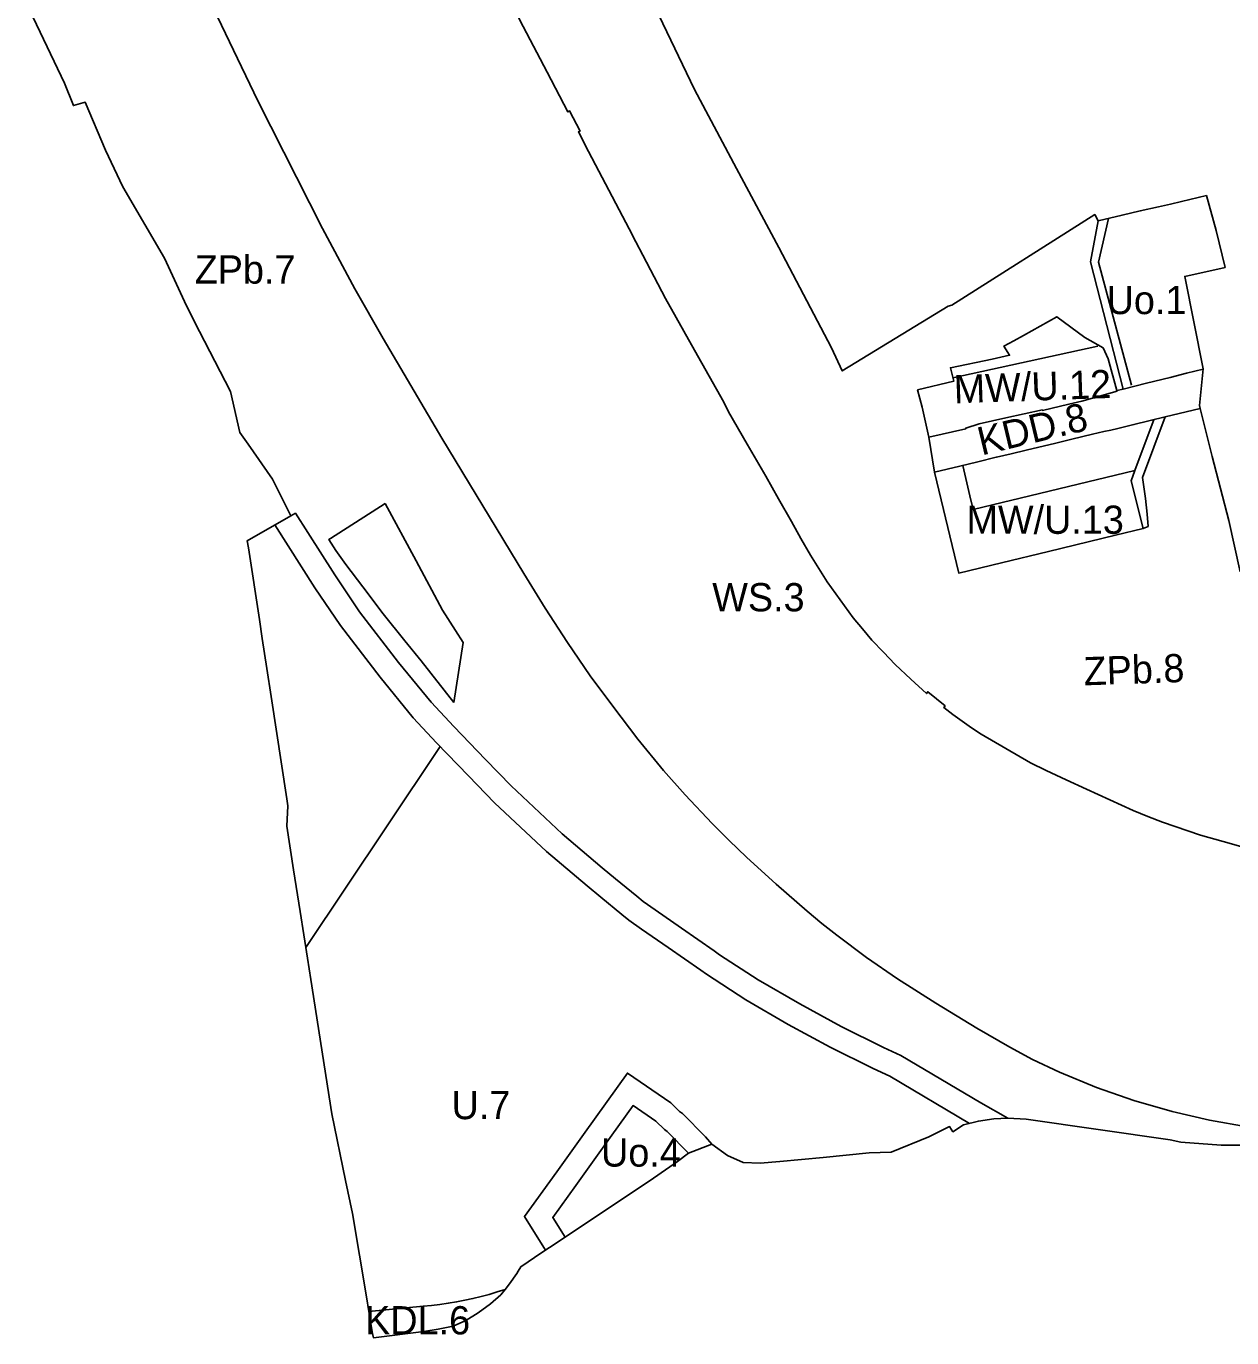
# Model space of a CAD drawing. Extents: x 7421697 to 7426767, y 5545731 to 5547485.
# Drawn here: x 7423591 to 7424103, y 5545804 to 5546361 of the extents above; entities that cross this region are included whole.
import ezdxf

# ---------------------------------------------------------------- set-up
doc = ezdxf.new("R2010")
doc.units = 0
for name, color, linetype in [('LIN_linia regulacyjna', 7, 'Continuous'), ('LIN_Linia Zabudowy Nieprzekraczalna', 7, 'Continuous'), ('LIN_linie_rozgraniczajace', 7, 'Continuous'), ('TXT_oznaczenia_przeznaczen', 7, 'Continuous')]:
    doc.layers.add(name, color=color, linetype=linetype)

msp = doc.modelspace()

# ---------------------------------------------------------------- linework, layer by layer
at = {"layer": 'LIN_linia regulacyjna'}
for p, q in [((7423766.42, 5546054.68), (7423743.61, 5546020.65)), ((7423743.61, 5546020.65), (7423709.27, 5545969.41))]:
    msp.add_line(p, q, dxfattribs=at)
for points in [[(7424063.77, 5546178.03), (7424069.56, 5546193.49)], [(7423991.42, 5546161.09), (7423992.75, 5546155.38), (7424061.5, 5546171.94), (7424063.77, 5546178.03)], [(7423988.4, 5546173.98), (7423991.42, 5546161.09)]]:
    msp.add_lwpolyline(points, dxfattribs=at)
at = {"layer": 'LIN_Linia Zabudowy Nieprzekraczalna'}
for p, q in [((7424045.78, 5546224.78), (7423984.11, 5546211.26)), ((7423743.06, 5546157.87), (7423719.82, 5546143.08)), ((7423772.2, 5546073.46), (7423776.13, 5546098.81))]:
    msp.add_line(p, q, dxfattribs=at)
for points in [[(7424050.23, 5546278.96), (7424045.99, 5546260.44), (7424060.07, 5546208.09)], [(7424064.95, 5546147.23), (7424059.83, 5546167.51), (7424061.49, 5546171.94)], [(7423776.13, 5546098.81), (7423772.84, 5546104.02), (7423767.4, 5546112.65), (7423756.15, 5546133.55), (7423743.06, 5546157.87)], [(7423991.24, 5545894.67), (7423957.33, 5545914.69), (7423950.32, 5545917.94), (7423932.02, 5545926.98), (7423914.18, 5545936.67), (7423896.14, 5545947.17), (7423879.49, 5545958.01), (7423877.03, 5545959.71), (7423863.17, 5545969.37), (7423851.94, 5545977.19), (7423846.5, 5545980.98), (7423843.54, 5545983.41), (7423834.56, 5545990.77), (7423828.77, 5545995.52), (7423811.54, 5546010.19), (7423789.48, 5546030.86), (7423778.4, 5546042.2), (7423764.84, 5546056.32), (7423754.96, 5546066.95), (7423740.85, 5546084.21), (7423724, 5546106.07), (7423713.19, 5546122.15), (7423696.2, 5546148.8)], [(7423719.82, 5546143.08), (7423719.07, 5546142.6), (7423722.11, 5546137.99), (7423726.32, 5546132), (7423733.5, 5546122.46), (7423742.18, 5546111.01), (7423751.29, 5546099.62), (7423758.29, 5546091.03), (7423772.2, 5546073.46)], [(7423811.08, 5545840.81), (7423802.15, 5545855.11), (7423815.91, 5545874.15), (7423827.93, 5545890.97), (7423845.89, 5545916), (7423864.38, 5545903.38), (7423868.08, 5545899.74), (7423869.35, 5545898.83), (7423879, 5545889), (7423881.73, 5545885.8)]]:
    msp.add_lwpolyline(points, dxfattribs=at)
at = {"layer": 'LIN_linie_rozgraniczajace'}
for points in [[(7423888.81, 5546196.87), (7423886.82, 5546200.98), (7423874.46, 5546223), (7423862.11, 5546245.01), (7423857.28, 5546254.19), (7423852.44, 5546263.37), (7423849.52, 5546268.96), (7423846.59, 5546274.55), (7423833.79, 5546299.08), (7423829.43, 5546307.39), (7423825.08, 5546315.69), (7423825.83, 5546316.03), (7423821.34, 5546324.6), (7423820.65, 5546324.21), (7423811.84, 5546341.04), (7423801.68, 5546360.42), (7423786.55, 5546389.63), (7423777.35, 5546407.77), (7423769.51, 5546423.7), (7423758.58, 5546446.87), (7423754.31, 5546456.24), (7423750.05, 5546465.61), (7423742.71, 5546481.91), (7423737.86, 5546492.89)], [(7424109.13, 5545893.25), (7424093.15, 5545896.05), (7424077.31, 5545899.76), (7424060.98, 5545904.43), (7424045.1, 5545909.88), (7424029.43, 5545916.36), (7424017.92, 5545921.85), (7424008.3, 5545926.98), (7423994.31, 5545935.05), (7423976.97, 5545945.7), (7423960.67, 5545956.05), (7423947.41, 5545965.11), (7423934.81, 5545974.58), (7423928.42, 5545979.6), (7423922.22, 5545984.79), (7423909.02, 5545996.25), (7423896.5, 5546007.68), (7423889.11, 5546014.73), (7423881.96, 5546022.03), (7423870.41, 5546034.24), (7423861.28, 5546044.45), (7423850.39, 5546057.76), (7423839.7, 5546071.82), (7423830.1, 5546084.79), (7423820.41, 5546098.84), (7423811, 5546113.42), (7423801.97, 5546128.12), (7423767.08, 5546185.68), (7423742.08, 5546228.03), (7423730.07, 5546249.1), (7423716.41, 5546274.66), (7423688.92, 5546328.84), (7423666.53, 5546375.63)], [(7424108.1, 5545885.42), (7424098.05, 5545885.35), (7424080.98, 5545886.74), (7424076.38, 5545887.66), (7424015.23, 5545896.5), (7424007.5, 5545896.87), (7424001.61, 5545896.53), (7423995.01, 5545895.67), (7423988.73, 5545894.01), (7423984.17, 5545891.11), (7423982.72, 5545893.33), (7423973.98, 5545888.99), (7423957.92, 5545882.39), (7423948.55, 5545882.22), (7423929.11, 5545880.16), (7423910.67, 5545878.55), (7423902.26, 5545877.74), (7423895.01, 5545878.1), (7423888.46, 5545881.02), (7423881.73, 5545885.8), (7423871.86, 5545881.99), (7423867.24, 5545878.49), (7423856.95, 5545871.34), (7423819.39, 5545846.37), (7423812.79, 5545841.95), (7423809.6, 5545839.82), (7423800.58, 5545833.77), (7423799.56, 5545831.85), (7423798.87, 5545830.86), (7423795.85, 5545826.51), (7423793.98, 5545824.18), (7423792.09, 5545821.84), (7423787.71, 5545818.07), (7423782.57, 5545814.23), (7423777.24, 5545810.97), (7423771.92, 5545808.58), (7423765.48, 5545807.26), (7423759.46, 5545806.26), (7423738, 5545803.63), (7423737.68, 5545805.5), (7423736.55, 5545812.22), (7423736.12, 5545814.75), (7423735.06, 5545821.05), (7423729.09, 5545856.42), (7423726.17, 5545870.48), (7423720.3, 5545898.69), (7423711.38, 5545955.82), (7423709.99, 5545964.79), (7423706.88, 5545984.7), (7423704.12, 5546002.34), (7423701.22, 5546020.93), (7423701.72, 5546029.57), (7423701.27, 5546032.53), (7423694.61, 5546075.92), (7423692.77, 5546087.84), (7423690.8, 5546100.64), (7423689.58, 5546108.6), (7423684.89, 5546139.1), (7423684.44, 5546142.05), (7423702.94, 5546152.67), (7423695.13, 5546168.29), (7423684.79, 5546183.08), (7423681.23, 5546188.06), (7423677.33, 5546205.48), (7423661.9, 5546235.37), (7423659.84, 5546239.38), (7423658.61, 5546241.81), (7423649.28, 5546262.07), (7423631.62, 5546292.35), (7423624.14, 5546307.98), (7423615.52, 5546328.33), (7423610.61, 5546326.9), (7423606.78, 5546336.34), (7423590.53, 5546370.45)], [(7423859.24, 5546365.27), (7423874.37, 5546333.67), (7423892.28, 5546300.17), (7423910.19, 5546266.66), (7423932.61, 5546223.95), (7423937.14, 5546214.2), (7423982.18, 5546241.75), (7423983.72, 5546242.11), (7424044.41, 5546280.59), (7424045.88, 5546277.87), (7424056.01, 5546280.41), (7424063.77, 5546282.17), (7424071.54, 5546283.94), (7424076.53, 5546285.07), (7424081.26, 5546286.15), (7424091.83, 5546288.66), (7424096, 5546273.89), (7424099.79, 5546258.14), (7424082.61, 5546254.35), (7424090.45, 5546215.13), (7424088.86, 5546199.57), (7424089.18, 5546198.28), (7424094.35, 5546177.91), (7424101.33, 5546150.7), (7424106.15, 5546128.94)], [(7424045.88, 5546277.87), (7424042.64, 5546260.52), (7424056.47, 5546206.44)], [(7423973.87, 5546186.1), (7423971.04, 5546198.75), (7423969.16, 5546206.19), (7423984.62, 5546209.86), (7423983.11, 5546215.52), (7424000.85, 5546219.26), (7424008.21, 5546220.87), (7424005.86, 5546224.76), (7424010, 5546227.03), (7424014.13, 5546229.29), (7424028.27, 5546237.18), (7424040.17, 5546228.42), (7424047.92, 5546224.03), (7424050.06, 5546219.38), (7424053.81, 5546205.84)], [(7424090.42, 5546214.9), (7424083.43, 5546213.19), (7424076.43, 5546211.47), (7424066.45, 5546208.96), (7424056.47, 5546206.44), (7424053.81, 5546205.84), (7424053.88, 5546205.61), (7424038.95, 5546201.4), (7424033.47, 5546200.06), (7424022.19, 5546197.45), (7424022.15, 5546197.62), (7424006.61, 5546194.24), (7423995.25, 5546191.78), (7423989.61, 5546189.93), (7423989.68, 5546189.64), (7423973.87, 5546186.1), (7423976.31, 5546171.16), (7423981.7, 5546172.44), (7423987.09, 5546173.71), (7423994.79, 5546175.61), (7424002.49, 5546177.51), (7424002.72, 5546177.57), (7424008.97, 5546179.03), (7424015.22, 5546180.49), (7424027.9, 5546183.56), (7424034.66, 5546185.15), (7424043.43, 5546187.32), (7424045.86, 5546187.87), (7424048.28, 5546188.42), (7424051.24, 5546189.09), (7424054.2, 5546189.77), (7424061.04, 5546191.41), (7424074.27, 5546194.64), (7424089.18, 5546198.28)], [(7424108.51, 5546011.67), (7424098.91, 5546014.37), (7424089.3, 5546017.07), (7424073.25, 5546022.52), (7424066.97, 5546025.02), (7424060.69, 5546027.52), (7424040.84, 5546036.57), (7424032.33, 5546040.52), (7424023.81, 5546044.48), (7424017.08, 5546047.82), (7424006.61, 5546053.87), (7423996.15, 5546059.92), (7423992.11, 5546062.68), (7423988.07, 5546065.44), (7423984.19, 5546068.34), (7423980.31, 5546071.25), (7423980.81, 5546071.92), (7423973.47, 5546077.95), (7423972.94, 5546077.21), (7423966.26, 5546083.37), (7423959.57, 5546089.52), (7423954.65, 5546094.71), (7423949.72, 5546099.9), (7423945.73, 5546104.66), (7423941.74, 5546109.41), (7423936.25, 5546117), (7423930.77, 5546124.59), (7423927.21, 5546130.24), (7423923.64, 5546135.9), (7423919.61, 5546143.05), (7423915.57, 5546150.2), (7423910.12, 5546159.82), (7423904.67, 5546169.44), (7423896.74, 5546183.15), (7423888.81, 5546196.87)], [(7423976.31, 5546171.16), (7423986.64, 5546128.34), (7424004.81, 5546132.72), (7424024.72, 5546137.52), (7424053.19, 5546144.39), (7424064.95, 5546147.23), (7424067.1, 5546148.16), (7424066.74, 5546153.35), (7424065.98, 5546160.09), (7424064.66, 5546169), (7424074.27, 5546194.64)], [(7423702.94, 5546152.67), (7423704.89, 5546153.79), (7423710.13, 5546145.56), (7423721.55, 5546127.63), (7423732.12, 5546111.91), (7423748.68, 5546090.43), (7423762.5, 5546073.53), (7423772.11, 5546063.19), (7423785.59, 5546049.15), (7423796.48, 5546038.01), (7423818.21, 5546017.65), (7423835.19, 5546003.19), (7423840.9, 5545998.5), (7423849.88, 5545991.15), (7423852.54, 5545988.96), (7423857.66, 5545985.4), (7423868.88, 5545977.58), (7423882.74, 5545967.92), (7423885.07, 5545966.3), (7423901.38, 5545955.69), (7423919.09, 5545945.39), (7423936.63, 5545935.86), (7423954.64, 5545926.96), (7423961.98, 5545923.55), (7423996.07, 5545903.43), (7424007.5, 5545896.87)], [(7423819.39, 5545846.37), (7423814.19, 5545854.7), (7423824.03, 5545868.31), (7423836.06, 5545885.15), (7423848.32, 5545902.24), (7423858.01, 5545895.62), (7423861.61, 5545892.08), (7423862.81, 5545891.21), (7423871.86, 5545881.99)], [(7423736.12, 5545814.75), (7423759.21, 5545816.99), (7423762.75, 5545817.33), (7423766.28, 5545817.75), (7423769.8, 5545818.26), (7423773.31, 5545818.85), (7423776.81, 5545819.53), (7423780.28, 5545820.3), (7423783.74, 5545821.14), (7423787.17, 5545822.07), (7423790.59, 5545823.08), (7423793.98, 5545824.18)]]:
    msp.add_lwpolyline(points, dxfattribs=at)

# ---------------------------------------------------------------- texts
at = {"layer": 'TXT_oznaczenia_przeznaczen'}
for s, p in [('ZPb.7', (7423662.07, 5546251.27)), ('Uo.1', (7424049.44, 5546238.32)), ('MW/U.13', (7423989.92, 5546145.02)), ('WS.3', (7423881.93, 5546112.11)), ('U.7', (7423771.2, 5545896.46)), ('Uo.4', (7423834.7, 5545876.32)), ('KDL.6', (7423734.48, 5545805.06))]:
    msp.add_text(s, height=12, dxfattribs=at).set_placement(p)
for s, rotation, p in [('MW/U.12', 1.9867, (7423984.73, 5546200.41)), ('KDD.8', 13.4848, (7423996.32, 5546178.24)), ('ZPb.8', 1.9636, (7424039.87, 5546080.65))]:
    msp.add_text(s, height=12, rotation=rotation, dxfattribs=at).set_placement(p)

doc.saveas('drawing.dxf')
